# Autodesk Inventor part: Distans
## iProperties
Created: 2001-12
Part Number: Distans
Material: Silicon Nitride
Document SubType Name: Modeling
Designer: Tobben
Control State: 0
Master: False
Checked Out: False
Shininess: 64.0
Length Units: 11269
Angle Units: 11279
Time Units: 11290
Mass Units: 11283
Length Display Precision: 3
Angle Display Precision: 2
Density: 0.0
Volumn: 0.0
Area: 0.0
PropertySet Name: Model Information
Author: Tobben
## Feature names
1. Extrusion1
2. Fillet1
3. Fillet2
